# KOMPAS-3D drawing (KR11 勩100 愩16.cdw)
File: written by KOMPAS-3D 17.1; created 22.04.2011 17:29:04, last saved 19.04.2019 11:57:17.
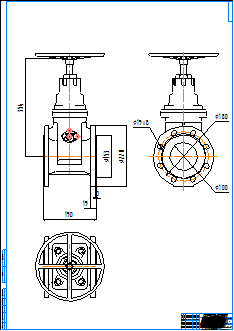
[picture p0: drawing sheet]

Title block, sheet 1: name: KR11 Ду100 Ру16; material: Внимание! Данный продукт является объектом авторского права ООО «Торговый Дом АДЛ». / Запрещается изменение, копирование, распространение / (в том числе путем копирования на другие сайты и ресурсы в Интернете) / или любое иное использование информации и объектов без предварительного / согласия правообладателя (ООО «Торговый Дом АДЛ»).; scale: 1:1; sheets: 1; organisation: ООО "Торговый дом АДЛ"; sheet format: A0; stored path: \\adlc.lan\data\АДЛ_ПКД\3D-модели\ADL production\Клиновые задвижки серии KR ГРАНАР\Клиновые задвижки KR11\KOMPAS 2D\KR11 Ду100 Ру16.cdw

Views: Спереди 4, Проекционный вид 5, Проекционный вид 6
Dimensions and other numbers on the sheet: 153; 220; 190; 19; 3; 354; 100; 180; 1:1; 1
